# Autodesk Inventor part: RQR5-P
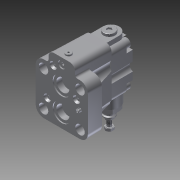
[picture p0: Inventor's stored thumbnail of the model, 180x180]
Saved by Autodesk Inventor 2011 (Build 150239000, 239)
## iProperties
Created: 2012-01
Part Number: RQR5-P
Document SubType Name: Modeling
Designer: khramov
Density: 1 g/cm^3
Author: khramov
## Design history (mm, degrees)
derived "RQR531.iam"
node "Твердое тело1"
node "0112482.ipt:1"
sketch "0550326.ipt:1"
sketch "0112484.ipt:1"
sketch "0571501.ipt:1"
sketch "0119296.ipt:1"
sketch "0530544.ipt:1"
sketch "0530329_ISO_24017___M8x40.ipt:1"
sketch "0530083_UNI_5931___M10x45.ipt:1"
sketch "0530083_UNI_5931___M10x45.ipt:2"
sketch "0530083_UNI_5931___M10x45.ipt:3"
sketch "0530083_UNI_5931___M10x45.ipt:4"
